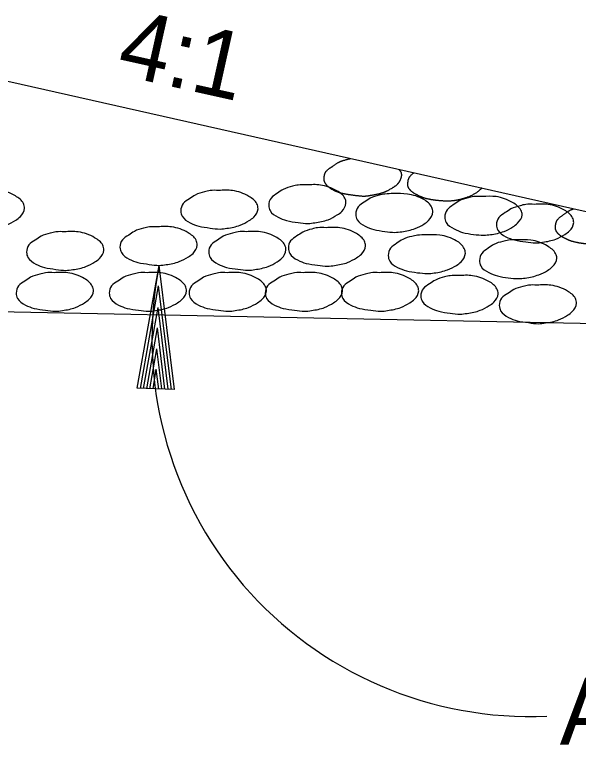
# Model space of a CAD drawing. Extents: x 714919 to 718439, y 1619644 to 1621844.
# Drawn here: x 717039.4 to 717165.2, y 1620546.1 to 1620713.5 of the extents above; entities that cross this region are included whole.
import ezdxf

# ---------------------------------------------------------------- set-up
doc = ezdxf.new("R2010")
doc.units = 0
doc.layers.add('Default', color=7, linetype='Continuous')

msp = doc.modelspace()

# ---------------------------------------------------------------- linework, layer by layer
at = {"layer": 'Default'}
for p, q in [((716978.32, 1620712.04), (717439.89, 1620608.12)), ((716381.27, 1620660.41), (717288.2, 1620642.27)), ((717066.63, 1620630.18), (717071.53, 1620657.6)), ((717074.94, 1620629.93), (717071.53, 1620657.6)), ((717067.37, 1620630.09), (717071.37, 1620653)), ((717074.27, 1620629.92), (717071.37, 1620653)), ((717068.04, 1620630.12), (717071.27, 1620648.23)), ((717073.53, 1620629.94), (717071.27, 1620648.23)), ((717068.78, 1620630.07), (717071.16, 1620643.66)), ((717072.82, 1620629.96), (717071.16, 1620643.66)), ((717069.45, 1620630.08), (717071, 1620638.98)), ((717072.11, 1620630.02), (717071, 1620638.98)), ((717070.17, 1620630.05), (717070.87, 1620634.41)), ((717071.45, 1620630), (717070.87, 1620634.41)), ((717074.94, 1620629.93), (717066.63, 1620630.18))]:
    msp.add_line(p, q, dxfattribs=at)
msp.add_arc((717154.17, 1620641.2), 84.25, 168.7799, 272.6238, dxfattribs=at)
for points in [[(717125.03, 1620679.01), (717125.06, 1620678.97), (717125.09, 1620678.93), (717125.12, 1620678.88), (717125.19, 1620678.8), (717125.25, 1620678.71), (717125.31, 1620678.61), (717125.37, 1620678.53), (717125.41, 1620678.44), (717125.46, 1620678.35), (717125.5, 1620678.26), (717125.52, 1620678.17), (717125.54, 1620678.07), (717125.56, 1620677.98), (717125.57, 1620677.89), (717125.58, 1620677.79), (717125.58, 1620677.75), (717125.58, 1620677.7), (717125.57, 1620677.66), (717125.57, 1620677.61), (717125.56, 1620677.57), (717125.55, 1620677.53), (717125.52, 1620677.36), (717125.48, 1620677.2), (717125.43, 1620677.04), (717125.38, 1620676.88), (717125.32, 1620676.72), (717125.24, 1620676.56), (717125.16, 1620676.4), (717125.08, 1620676.25), (717124.98, 1620676.1), (717124.93, 1620676.02), (717124.87, 1620675.95), (717124.81, 1620675.88), (717124.75, 1620675.81), (717124.69, 1620675.74), (717124.63, 1620675.67), (717124.47, 1620675.51), (717124.31, 1620675.36), (717124.12, 1620675.24), (717123.95, 1620675.11), (717123.77, 1620675), (717123.58, 1620674.89), (717123.26, 1620674.69), (717122.93, 1620674.49), (717122.6, 1620674.31), (717122.43, 1620674.22), (717122.27, 1620674.14), (717122.09, 1620674.06), (717122.01, 1620674.02), (717121.92, 1620673.98), (717121.83, 1620673.94), (717121.75, 1620673.91), (717121.66, 1620673.87), (717121.57, 1620673.84), (717121.33, 1620673.76), (717121.09, 1620673.68), (717120.84, 1620673.61), (717120.6, 1620673.55), (717120.36, 1620673.48), (717120.11, 1620673.43), (717119.87, 1620673.38), (717119.62, 1620673.33), (717119.37, 1620673.28), (717119.12, 1620673.24), (717118.88, 1620673.2), (717118.63, 1620673.16), (717118.37, 1620673.11), (717118.12, 1620673.07), (717117.86, 1620673.04), (717117.73, 1620673.02), (717117.61, 1620673.01), (717117.48, 1620673), (717117.35, 1620672.99), (717117.22, 1620672.99), (717117.1, 1620672.99), (717116.72, 1620673.01), (717116.35, 1620673.03), (717115.98, 1620673.08), (717115.6, 1620673.12), (717115.23, 1620673.16), (717114.86, 1620673.22), (717114.65, 1620673.24), (717114.44, 1620673.27), (717114.22, 1620673.31), (717114.01, 1620673.34), (717113.8, 1620673.37), (717113.59, 1620673.4), (717113.38, 1620673.44), (717113.17, 1620673.48), (717112.96, 1620673.52), (717112.74, 1620673.55), (717112.53, 1620673.6), (717112.32, 1620673.64), (717112.16, 1620673.67), (717111.99, 1620673.72), (717111.83, 1620673.77), (717111.67, 1620673.82), (717111.51, 1620673.88), (717111.35, 1620673.94), (717111.19, 1620674.01), (717111.03, 1620674.08), (717110.88, 1620674.15), (717110.72, 1620674.23), (717110.56, 1620674.3), (717110.41, 1620674.38), (717110.24, 1620674.47), (717110.07, 1620674.56), (717109.91, 1620674.66), (717109.75, 1620674.76), (717109.59, 1620674.86), (717109.45, 1620674.98), (717109.3, 1620675.1), (717109.16, 1620675.23), (717109.03, 1620675.37), (717108.96, 1620675.44), (717108.89, 1620675.52), (717108.83, 1620675.6), (717108.8, 1620675.64), (717108.76, 1620675.68), (717108.73, 1620675.72), (717108.7, 1620675.76), (717108.67, 1620675.81), (717108.64, 1620675.85), (717108.57, 1620675.95), (717108.52, 1620676.04), (717108.48, 1620676.14), (717108.43, 1620676.24), (717108.4, 1620676.34), (717108.38, 1620676.44), (717108.36, 1620676.53), (717108.35, 1620676.63), (717108.34, 1620676.73), (717108.33, 1620676.83), (717108.33, 1620676.93), (717108.34, 1620677.02), (717108.34, 1620677.16), (717108.35, 1620677.3), (717108.36, 1620677.44), (717108.38, 1620677.59), (717108.4, 1620677.73), (717108.44, 1620677.87), (717108.48, 1620678.01), (717108.53, 1620678.15), (717108.59, 1620678.28), (717108.63, 1620678.35), (717108.67, 1620678.42), (717108.71, 1620678.48), (717108.73, 1620678.51), (717108.76, 1620678.55), (717108.78, 1620678.58), (717108.81, 1620678.61), (717108.83, 1620678.64), (717108.86, 1620678.67), (717109.07, 1620678.9), (717109.3, 1620679.1), (717109.55, 1620679.28), (717109.61, 1620679.32), (717109.67, 1620679.36), (717109.73, 1620679.39), (717109.79, 1620679.43), (717109.85, 1620679.47), (717109.91, 1620679.51), (717109.97, 1620679.55), (717110.03, 1620679.58), (717110.09, 1620679.62), (717110.15, 1620679.66), (717110.21, 1620679.7), (717110.27, 1620679.74), (717110.48, 1620679.88), (717110.69, 1620680.04), (717110.9, 1620680.18), (717111.11, 1620680.33), (717111.33, 1620680.46), (717111.56, 1620680.59), (717111.64, 1620680.63), (717111.72, 1620680.67), (717111.8, 1620680.71), (717111.88, 1620680.75), (717111.97, 1620680.78), (717112.05, 1620680.82), (717112.22, 1620680.88), (717112.39, 1620680.94), (717112.56, 1620680.99), (717112.91, 1620681.1), (717113.26, 1620681.2), (717113.61, 1620681.29), (717113.72, 1620681.32), (717113.82, 1620681.35), (717113.93, 1620681.38), (717114.02, 1620681.4), (717114.11, 1620681.42), (717114.2, 1620681.45)], [(717143.48, 1620674.85), (717143.47, 1620674.84), (717143.46, 1620674.83), (717143.45, 1620674.81), (717143.39, 1620674.74), (717143.33, 1620674.67), (717143.26, 1620674.6), (717143.1, 1620674.43), (717142.93, 1620674.27), (717142.75, 1620674.13), (717142.57, 1620673.99), (717142.39, 1620673.87), (717142.19, 1620673.75), (717141.88, 1620673.56), (717141.57, 1620673.38), (717141.25, 1620673.22), (717140.93, 1620673.06), (717140.6, 1620672.91), (717140.26, 1620672.78), (717140.01, 1620672.69), (717139.76, 1620672.61), (717139.51, 1620672.53), (717139.26, 1620672.45), (717139.01, 1620672.38), (717138.76, 1620672.31), (717138.5, 1620672.25), (717138.25, 1620672.19), (717137.99, 1620672.14), (717137.87, 1620672.12), (717137.74, 1620672.09), (717137.61, 1620672.07), (717137.48, 1620672.05), (717137.35, 1620672.03), (717137.22, 1620672.02), (717136.97, 1620671.99), (717136.72, 1620671.97), (717136.47, 1620671.95), (717136.23, 1620671.94), (717135.98, 1620671.93), (717135.73, 1620671.94), (717135.35, 1620671.94), (717134.97, 1620671.96), (717134.59, 1620671.98), (717134.21, 1620672.01), (717133.83, 1620672.04), (717133.45, 1620672.08), (717133.25, 1620672.1), (717133.04, 1620672.13), (717132.83, 1620672.16), (717132.63, 1620672.19), (717132.42, 1620672.22), (717132.22, 1620672.26), (717132.01, 1620672.29), (717131.81, 1620672.34), (717131.61, 1620672.38), (717131.4, 1620672.42), (717131.2, 1620672.47), (717131, 1620672.52), (717130.83, 1620672.56), (717130.66, 1620672.61), (717130.5, 1620672.67), (717130.34, 1620672.73), (717130.18, 1620672.79), (717130.02, 1620672.86), (717129.86, 1620672.93), (717129.71, 1620673), (717129.55, 1620673.07), (717129.39, 1620673.15), (717129.24, 1620673.23), (717129.08, 1620673.31), (717128.91, 1620673.39), (717128.75, 1620673.48), (717128.58, 1620673.58), (717128.42, 1620673.67), (717128.27, 1620673.77), (717128.12, 1620673.88), (717127.96, 1620673.99), (717127.82, 1620674.11), (717127.69, 1620674.25), (717127.62, 1620674.32), (717127.55, 1620674.39), (717127.49, 1620674.47), (717127.45, 1620674.51), (717127.42, 1620674.55), (717127.39, 1620674.59), (717127.35, 1620674.63), (717127.32, 1620674.67), (717127.29, 1620674.72), (717127.22, 1620674.81), (717127.17, 1620674.92), (717127.12, 1620675.03), (717127.07, 1620675.13), (717127.04, 1620675.24), (717127.03, 1620675.35), (717127.01, 1620675.45), (717126.99, 1620675.56), (717126.99, 1620675.67), (717126.99, 1620675.78), (717127, 1620675.88), (717127.01, 1620675.99), (717127.02, 1620676.12), (717127.04, 1620676.25), (717127.06, 1620676.38), (717127.08, 1620676.52), (717127.11, 1620676.65), (717127.15, 1620676.78), (717127.19, 1620676.91), (717127.24, 1620677.04), (717127.31, 1620677.17), (717127.34, 1620677.23), (717127.38, 1620677.3), (717127.42, 1620677.36), (717127.44, 1620677.39), (717127.46, 1620677.42), (717127.48, 1620677.45), (717127.5, 1620677.48), (717127.53, 1620677.51), (717127.55, 1620677.54), (717127.75, 1620677.77), (717127.97, 1620677.99), (717128.21, 1620678.17), (717128.25, 1620678.2), (717128.3, 1620678.23), (717128.34, 1620678.26)], [(717177.19, 1620667.27), (717177.21, 1620667.2), (717177.22, 1620667.13), (717177.22, 1620667.06), (717177.23, 1620667.02), (717177.23, 1620666.98), (717177.23, 1620666.94), (717177.22, 1620666.9), (717177.22, 1620666.86), (717177.21, 1620666.82), (717177.18, 1620666.65), (717177.13, 1620666.49), (717177.07, 1620666.33), (717177.01, 1620666.16), (717176.94, 1620666), (717176.86, 1620665.85), (717176.77, 1620665.69), (717176.67, 1620665.53), (717176.56, 1620665.38), (717176.51, 1620665.31), (717176.45, 1620665.23), (717176.39, 1620665.16), (717176.33, 1620665.09), (717176.27, 1620665.01), (717176.2, 1620664.94), (717176.05, 1620664.77), (717175.88, 1620664.61), (717175.69, 1620664.46), (717175.52, 1620664.32), (717175.33, 1620664.19), (717175.14, 1620664.08), (717174.82, 1620663.89), (717174.51, 1620663.7), (717174.18, 1620663.54), (717173.86, 1620663.38), (717173.53, 1620663.23), (717173.18, 1620663.11), (717172.93, 1620663.02), (717172.68, 1620662.94), (717172.43, 1620662.87), (717172.18, 1620662.79), (717171.93, 1620662.72), (717171.68, 1620662.66), (717171.3, 1620662.57), (717170.92, 1620662.49), (717170.53, 1620662.42), (717170.4, 1620662.4), (717170.27, 1620662.38), (717170.14, 1620662.36), (717169.9, 1620662.33), (717169.65, 1620662.3), (717169.41, 1620662.29), (717169.16, 1620662.27), (717168.92, 1620662.26), (717168.67, 1620662.26), (717168.48, 1620662.27), (717168.29, 1620662.27), (717168.1, 1620662.28), (717167.91, 1620662.29), (717167.71, 1620662.3), (717167.52, 1620662.32), (717167.14, 1620662.35), (717166.76, 1620662.38), (717166.38, 1620662.42), (717166.17, 1620662.45), (717165.97, 1620662.48), (717165.76, 1620662.51), (717165.56, 1620662.54), (717165.35, 1620662.57), (717165.15, 1620662.61), (717164.95, 1620662.65), (717164.75, 1620662.69), (717164.54, 1620662.73), (717164.34, 1620662.77), (717164.14, 1620662.82), (717163.94, 1620662.87), (717163.77, 1620662.91), (717163.6, 1620662.96), (717163.44, 1620663.02), (717163.27, 1620663.07), (717163.11, 1620663.13), (717162.95, 1620663.2), (717162.79, 1620663.27), (717162.64, 1620663.34), (717162.48, 1620663.42), (717162.32, 1620663.49), (717162.16, 1620663.57), (717162.01, 1620663.65), (717161.84, 1620663.74), (717161.67, 1620663.83), (717161.51, 1620663.92), (717161.35, 1620664.01), (717161.2, 1620664.11), (717161.05, 1620664.22), (717160.9, 1620664.34), (717160.76, 1620664.46), (717160.62, 1620664.59), (717160.55, 1620664.66), (717160.49, 1620664.74), (717160.42, 1620664.81), (717160.39, 1620664.85), (717160.36, 1620664.89), (717160.33, 1620664.93), (717160.29, 1620664.98), (717160.26, 1620665.02), (717160.23, 1620665.06), (717160.17, 1620665.16), (717160.11, 1620665.26), (717160.06, 1620665.37), (717160.02, 1620665.47), (717159.99, 1620665.58), (717159.97, 1620665.68), (717159.96, 1620665.79), (717159.94, 1620665.89), (717159.94, 1620666), (717159.94, 1620666.1), (717159.94, 1620666.21), (717159.95, 1620666.31), (717159.96, 1620666.45), (717159.97, 1620666.58), (717159.99, 1620666.71), (717160.01, 1620666.85), (717160.04, 1620666.98), (717160.08, 1620667.12), (717160.11, 1620667.25), (717160.16, 1620667.39), (717160.23, 1620667.51), (717160.26, 1620667.58), (717160.3, 1620667.64), (717160.34, 1620667.7), (717160.36, 1620667.73), (717160.38, 1620667.76), (717160.4, 1620667.79), (717160.43, 1620667.82), (717160.45, 1620667.85), (717160.47, 1620667.88), (717160.68, 1620668.11), (717160.9, 1620668.33), (717161.15, 1620668.51), (717161.39, 1620668.68), (717161.63, 1620668.84), (717161.86, 1620669.01), (717162.08, 1620669.17), (717162.29, 1620669.33), (717162.5, 1620669.48), (717162.61, 1620669.56), (717162.72, 1620669.63), (717162.83, 1620669.7), (717162.88, 1620669.74), (717162.94, 1620669.77), (717163, 1620669.8), (717163.05, 1620669.84), (717163.11, 1620669.87), (717163.17, 1620669.9), (717163.33, 1620669.97), (717163.49, 1620670.04), (717163.65, 1620670.1), (717163.77, 1620670.15), (717163.89, 1620670.19), (717164.01, 1620670.23)]]:
    msp.add_open_spline(points, degree=3, dxfattribs=at)
for points in [[(717104.41, 1620675.55), (717107.49, 1620675.53), (717111.16, 1620674.24), (717112.95, 1620672.57), (717113.19, 1620671.48), (717112.27, 1620669.63), (717111.22, 1620668.84), (717109.21, 1620667.79), (717106.27, 1620667.11), (717104.73, 1620666.95), (717102.5, 1620667.17), (717099.96, 1620667.59), (717098.05, 1620668.34), (717096.28, 1620669.81), (717095.97, 1620670.97), (717096.5, 1620672.63), (717097.91, 1620673.69), (717099.2, 1620674.54), (717101.25, 1620675.24), (717102.52, 1620675.53), (717104.41, 1620675.55)], [(717032.7, 1620674.4), (717035.79, 1620674.38), (717039.45, 1620673.09), (717041.24, 1620671.42), (717041.49, 1620670.33), (717040.56, 1620668.48), (717039.51, 1620667.69), (717037.5, 1620666.65), (717034.56, 1620665.96), (717033.03, 1620665.8), (717030.79, 1620666.02), (717028.25, 1620666.45), (717026.34, 1620667.19), (717024.57, 1620668.66), (717024.27, 1620669.83), (717024.79, 1620671.48), (717026.2, 1620672.55), (717027.49, 1620673.39), (717029.54, 1620674.1), (717030.81, 1620674.38), (717032.7, 1620674.4)], [(717084.79, 1620674.31), (717087.88, 1620674.29), (717091.54, 1620673), (717093.33, 1620671.33), (717093.58, 1620670.24), (717092.65, 1620668.39), (717091.6, 1620667.6), (717089.59, 1620666.55), (717086.65, 1620665.87), (717085.12, 1620665.71), (717082.88, 1620665.93), (717080.34, 1620666.35), (717078.43, 1620667.1), (717076.66, 1620668.57), (717076.36, 1620669.73), (717076.88, 1620671.39), (717078.29, 1620672.45), (717079.58, 1620673.3), (717081.63, 1620674), (717082.9, 1620674.29), (717084.79, 1620674.31)], [(717123.79, 1620673.61), (717126.9, 1620673.51), (717130.56, 1620672.28), (717132.35, 1620670.53), (717132.58, 1620669.52), (717131.63, 1620667.61), (717130.6, 1620666.8), (717128.63, 1620665.81), (717125.65, 1620665.11), (717124.1, 1620664.97), (717121.88, 1620665.17), (717119.42, 1620665.61), (717117.47, 1620666.36), (717115.7, 1620667.77), (717115.38, 1620669), (717115.92, 1620670.65), (717117.29, 1620671.71), (717118.62, 1620672.6), (717120.61, 1620673.27), (717121.9, 1620673.51), (717123.79, 1620673.61)], [(717143.64, 1620672.95), (717146.7, 1620672.93), (717150.37, 1620671.64), (717152.22, 1620669.91), (717152.5, 1620668.9), (717151.49, 1620667.03), (717150.43, 1620666.18), (717148.47, 1620665.19), (717145.43, 1620664.45), (717143.96, 1620664.35), (717141.67, 1620664.51), (717139.23, 1620664.95), (717137.32, 1620665.74), (717135.52, 1620667.15), (717135.24, 1620668.39), (717135.76, 1620669.97), (717137.15, 1620671.09), (717138.46, 1620671.98), (717140.44, 1620672.64), (717141.71, 1620672.93), (717143.64, 1620672.95)], [(717155.22, 1620671.21), (717158.31, 1620671.19), (717161.97, 1620669.9), (717163.76, 1620668.23), (717164, 1620667.14), (717163.08, 1620665.29), (717162.03, 1620664.51), (717160.02, 1620663.46), (717157.08, 1620662.77), (717155.55, 1620662.61), (717153.31, 1620662.83), (717150.77, 1620663.26), (717148.86, 1620664), (717147.09, 1620665.47), (717146.78, 1620666.64), (717147.31, 1620668.29), (717148.72, 1620669.36), (717150.01, 1620670.21), (717152.06, 1620670.91), (717153.33, 1620671.19), (717155.22, 1620671.21)], [(717071.22, 1620666.2), (717074.3, 1620666.18), (717077.97, 1620664.89), (717079.76, 1620663.22), (717080, 1620662.13), (717079.08, 1620660.28), (717078.03, 1620659.5), (717076.02, 1620658.45), (717073.07, 1620657.76), (717071.54, 1620657.6), (717069.31, 1620657.82), (717066.77, 1620658.25), (717064.86, 1620658.99), (717063.09, 1620660.46), (717062.78, 1620661.63), (717063.31, 1620663.28), (717064.72, 1620664.35), (717066.01, 1620665.19), (717068.06, 1620665.9), (717069.33, 1620666.18), (717071.22, 1620666.2)], [(717108.77, 1620666.01), (717111.86, 1620665.99), (717115.52, 1620664.7), (717117.31, 1620663.03), (717117.56, 1620661.94), (717116.63, 1620660.09), (717115.58, 1620659.3), (717113.57, 1620658.25), (717110.63, 1620657.57), (717109.1, 1620657.41), (717106.86, 1620657.63), (717104.32, 1620658.05), (717102.41, 1620658.8), (717100.64, 1620660.27), (717100.34, 1620661.44), (717100.86, 1620663.09), (717102.27, 1620664.16), (717103.56, 1620665), (717105.61, 1620665.71), (717106.88, 1620665.99), (717108.77, 1620666.01)], [(717050.39, 1620665.09), (717053.47, 1620665.07), (717057.13, 1620663.78), (717058.93, 1620662.11), (717059.17, 1620661.02), (717058.24, 1620659.16), (717057.19, 1620658.38), (717055.18, 1620657.33), (717052.24, 1620656.65), (717050.71, 1620656.49), (717048.47, 1620656.71), (717045.94, 1620657.13), (717044.02, 1620657.88), (717042.25, 1620659.35), (717041.95, 1620660.51), (717042.47, 1620662.17), (717043.88, 1620663.23), (717045.17, 1620664.08), (717047.23, 1620664.78), (717048.49, 1620665.07), (717050.39, 1620665.09)], [(717091.02, 1620665.1), (717094.1, 1620665.08), (717097.77, 1620663.79), (717099.56, 1620662.12), (717099.8, 1620661.03), (717098.88, 1620659.18), (717097.83, 1620658.39), (717095.82, 1620657.35), (717092.87, 1620656.66), (717091.34, 1620656.5), (717089.11, 1620656.72), (717086.57, 1620657.14), (717084.66, 1620657.89), (717082.89, 1620659.36), (717082.58, 1620660.53), (717083.11, 1620662.18), (717084.52, 1620663.25), (717085.81, 1620664.09), (717087.86, 1620664.8), (717089.13, 1620665.08), (717091.02, 1620665.1)], [(717131.04, 1620664.4), (717134.15, 1620664.32), (717137.81, 1620663.09), (717139.6, 1620661.34), (717139.83, 1620660.34), (717138.88, 1620658.42), (717137.85, 1620657.6), (717135.88, 1620656.63), (717132.9, 1620655.91), (717131.35, 1620655.78), (717129.13, 1620655.97), (717126.67, 1620656.41), (717124.72, 1620657.15), (717122.95, 1620658.56), (717122.63, 1620659.79), (717123.17, 1620661.46), (717124.54, 1620662.53), (717125.87, 1620663.4), (717127.86, 1620664.06), (717129.15, 1620664.32), (717131.04, 1620664.4)], [(717151.39, 1620663.26), (717154.45, 1620663.22), (717158.12, 1620661.93), (717159.97, 1620660.22), (717160.25, 1620659.21), (717159.25, 1620657.32), (717158.18, 1620656.47), (717156.23, 1620655.51), (717153.19, 1620654.76), (717151.72, 1620654.66), (717149.42, 1620654.82), (717146.98, 1620655.24), (717145.07, 1620656.03), (717143.28, 1620657.46), (717142.99, 1620658.71), (717143.52, 1620660.28), (717144.91, 1620661.41), (717146.22, 1620662.29), (717148.19, 1620662.94), (717149.46, 1620663.22), (717151.39, 1620663.26)], [(717048.07, 1620655.96), (717051.15, 1620655.94), (717054.82, 1620654.65), (717056.61, 1620652.98), (717056.85, 1620651.89), (717055.92, 1620650.04), (717054.88, 1620649.26), (717052.86, 1620648.21), (717049.92, 1620647.52), (717048.39, 1620647.36), (717046.16, 1620647.58), (717043.62, 1620648.01), (717041.7, 1620648.75), (717039.93, 1620650.22), (717039.63, 1620651.39), (717040.15, 1620653.04), (717041.56, 1620654.11), (717042.85, 1620654.96), (717044.91, 1620655.66), (717046.18, 1620655.94), (717048.07, 1620655.96)], [(717068.83, 1620655.96), (717071.91, 1620655.94), (717075.57, 1620654.65), (717077.37, 1620652.98), (717077.61, 1620651.89), (717076.68, 1620650.04), (717075.63, 1620649.26), (717073.62, 1620648.21), (717070.68, 1620647.52), (717069.15, 1620647.36), (717066.91, 1620647.58), (717064.38, 1620648.01), (717062.46, 1620648.75), (717060.69, 1620650.22), (717060.39, 1620651.39), (717060.91, 1620653.04), (717062.32, 1620654.11), (717063.61, 1620654.96), (717065.67, 1620655.66), (717066.93, 1620655.94), (717068.83, 1620655.96)], [(717086.66, 1620655.96), (717089.74, 1620655.94), (717093.41, 1620654.65), (717095.2, 1620652.98), (717095.44, 1620651.89), (717094.52, 1620650.04), (717093.47, 1620649.26), (717091.45, 1620648.21), (717088.51, 1620647.52), (717086.98, 1620647.36), (717084.75, 1620647.58), (717082.21, 1620648.01), (717080.3, 1620648.75), (717078.52, 1620650.22), (717078.22, 1620651.39), (717078.75, 1620653.04), (717080.16, 1620654.11), (717081.44, 1620654.96), (717083.5, 1620655.66), (717084.77, 1620655.94), (717086.66, 1620655.96)], [(717103.64, 1620655.96), (717106.72, 1620655.94), (717110.39, 1620654.65), (717112.18, 1620652.98), (717112.42, 1620651.89), (717111.49, 1620650.04), (717110.45, 1620649.26), (717108.43, 1620648.21), (717105.49, 1620647.52), (717103.96, 1620647.36), (717101.73, 1620647.58), (717099.19, 1620648.01), (717097.27, 1620648.75), (717095.5, 1620650.22), (717095.2, 1620651.39), (717095.72, 1620653.04), (717097.13, 1620654.11), (717098.42, 1620654.96), (717100.48, 1620655.66), (717101.75, 1620655.94), (717103.64, 1620655.96)], [(717120.64, 1620655.96), (717123.72, 1620655.94), (717127.38, 1620654.65), (717129.18, 1620652.98), (717129.42, 1620651.89), (717128.49, 1620650.04), (717127.44, 1620649.26), (717125.43, 1620648.21), (717122.49, 1620647.52), (717120.96, 1620647.36), (717118.72, 1620647.58), (717116.19, 1620648.01), (717114.27, 1620648.75), (717112.5, 1620650.22), (717112.2, 1620651.39), (717112.72, 1620653.04), (717114.13, 1620654.11), (717115.42, 1620654.96), (717117.48, 1620655.66), (717118.74, 1620655.94), (717120.64, 1620655.96)], [(717138.35, 1620655.32), (717141.43, 1620655.3), (717145.1, 1620654.01), (717146.89, 1620652.34), (717147.13, 1620651.25), (717146.21, 1620649.4), (717145.16, 1620648.61), (717143.15, 1620647.57), (717140.21, 1620646.88), (717138.68, 1620646.72), (717136.44, 1620646.94), (717133.9, 1620647.36), (717131.99, 1620648.11), (717130.22, 1620649.58), (717129.91, 1620650.75), (717130.44, 1620652.4), (717131.85, 1620653.47), (717133.14, 1620654.31), (717135.19, 1620655.02), (717136.46, 1620655.3), (717138.35, 1620655.32)], [(717155.85, 1620653.19), (717158.93, 1620653.17), (717162.59, 1620651.88), (717164.39, 1620650.21), (717164.63, 1620649.13), (717163.7, 1620647.27), (717162.65, 1620646.49), (717160.64, 1620645.44), (717157.7, 1620644.76), (717156.17, 1620644.59), (717153.93, 1620644.82), (717151.4, 1620645.24), (717149.48, 1620645.98), (717147.71, 1620647.45), (717147.41, 1620648.62), (717147.93, 1620650.27), (717149.34, 1620651.34), (717150.63, 1620652.19), (717152.68, 1620652.89), (717153.95, 1620653.17), (717155.85, 1620653.19)]]:
    msp.add_spline(points, degree=3, dxfattribs=at)

# ---------------------------------------------------------------- texts
msp.add_text('4:1', height=15, rotation=347.4212, dxfattribs=at).set_placement((717061.68, 1620700.3))
msp.add_text('AGG. BASE C0URSE (CLASS 7 ', height=15, dxfattribs=at).set_placement((717160.88, 1620550.63))

doc.saveas('drawing.dxf')
